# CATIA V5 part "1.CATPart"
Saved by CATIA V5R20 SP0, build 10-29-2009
Part number: 1
Bounding box of the stored display mesh (mm): x -155.915 to 155.43, y -220 to 220, z -155.943 to 155.339
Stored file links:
  E:\Ehsan\Amoozesh\CATIA\CATIA Course\Advanced\Videos\Session-22\1.CATPart
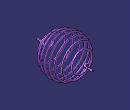
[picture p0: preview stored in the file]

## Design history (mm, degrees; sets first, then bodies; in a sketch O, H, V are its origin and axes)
AxisSystem1: origin (0, 0, 0), X (1, 0, 0), Y (0, 1, 0), Z (0, 0, 1)
Set1
  Helix1: Direction edge [YZ plane of AxisSystem1 | XY plane of AxisSystem1], RefPoint Sketch1.P1, Pitch 36, Height 440, TaperAngle 0, RadiusLaw Sketch1
  Sweep1: type Circle, Guide Helix1, Radius 6
  CloseSurface1: CloseElement Sweep1
Body1 (main body)
  Sketch1 on YZ plane of AxisSystem1, origin (0, 0, 0), H (0, 1, 0), V (0, 0, 1)
    point P1 (-220, 0)
    line L1 (-220, 0) -> (-181.659, 0)
    point P2 (-150, 0)
    arc A1 centre (0, 0) radius 150 from (-147.2911, -28.3784) to (147.2911, -28.3784) ccw
    arc A2 centre (-181.659, -35) radius 35 from (-181.659, 0) to (-147.2911, -28.3784) cw
    point P3 (-181.659, 0)
    point P4 (-147.2911, -28.3784)
    point P6 (147.2911, -28.3784)
    point P7 (181.659, 0)
    arc A3 centre (181.659, -35) radius 35 from (181.659, 0) to (147.2911, -28.3784) ccw
    point P9 (220, 0)
    line L2 (220, 0) -> (181.659, 0)
    radius A1 = 150
    distance P1 P2 = 70
    radius A2 = 35
    coincidence: P1 H, L1 P2, A1 P2
    horizontal: L1 H
    tangency: A2 L1, A2 A1
    symmetry: P4 P6 V, P3 P7 V, A2 A3 V, P1 P9 V, L1 L2 V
